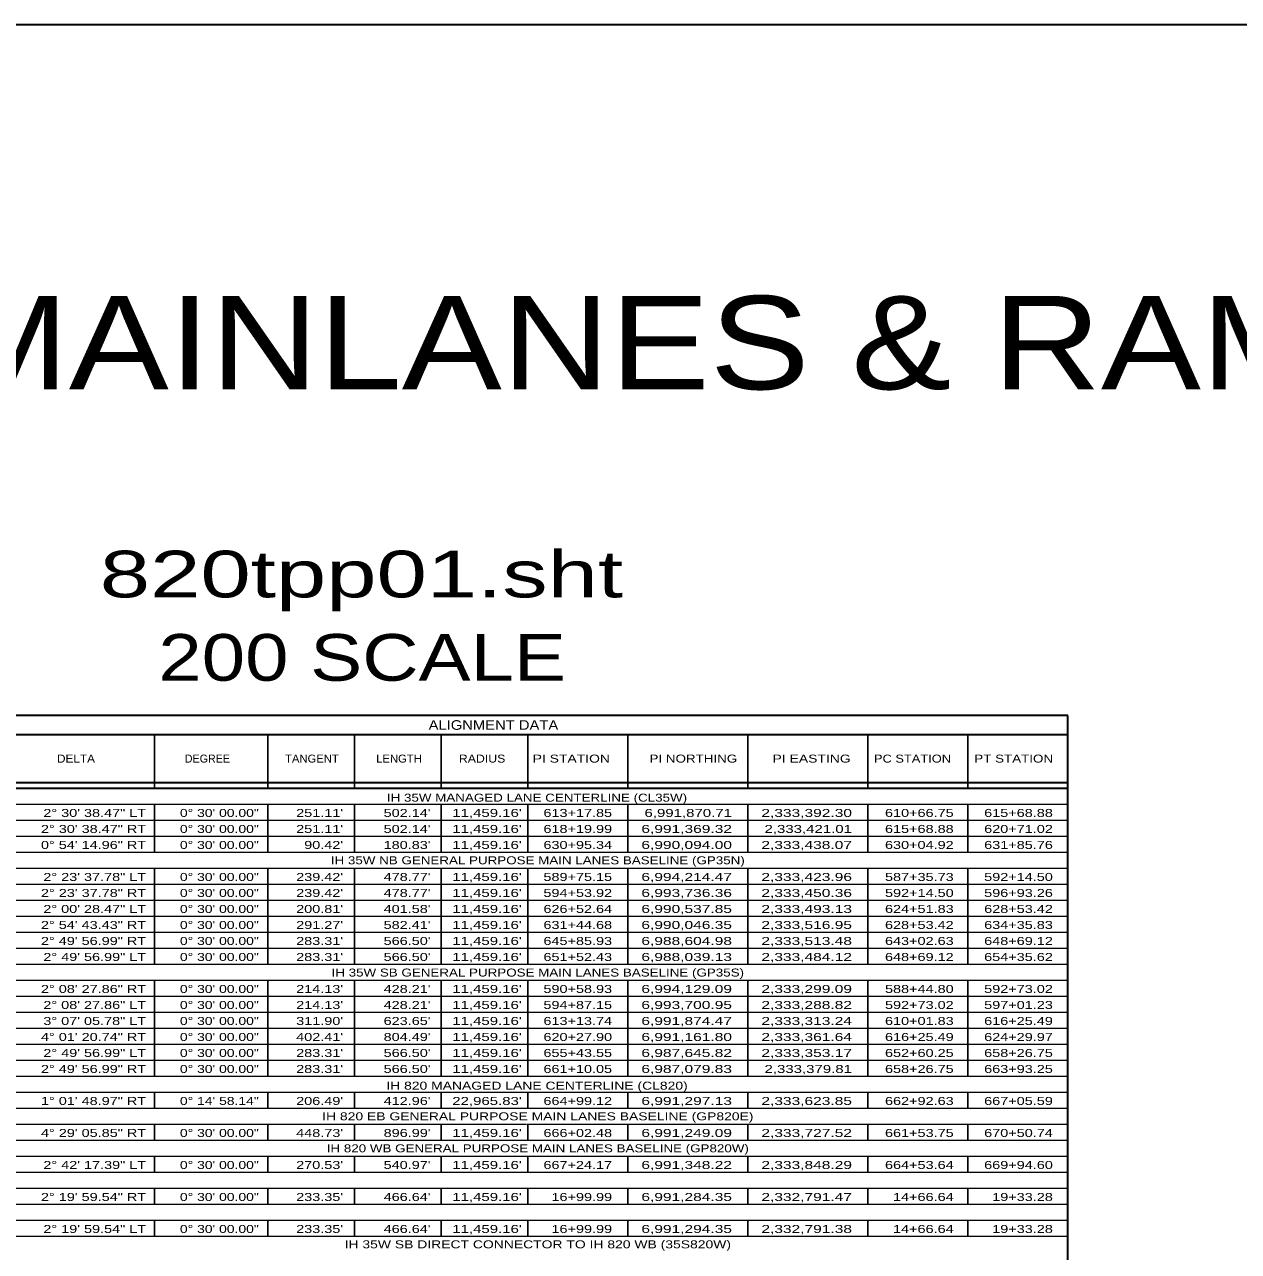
# Model space of a CAD drawing. Extents: x 1953053 to 1967065, y 7363860 to 7371201.
# Drawn here: x 1954045 to 1955866, y 7369361 to 7371201 of the extents above; entities that cross this region are included whole.
import ezdxf
from ezdxf.enums import TextEntityAlignment as Align

# ---------------------------------------------------------------- set-up
doc = ezdxf.new("R2010")
doc.units = 0
doc.header["$LTSCALE"] = 4.8
doc.layers.add('10', color=7, linetype='Continuous')
doc.layers.add('12', color=7, linetype='Continuous', lineweight=25)
doc.layers.add('62', color=7, linetype='Continuous', lineweight=35)

msp = doc.modelspace()

# ---------------------------------------------------------------- linework, layer by layer
at = {"layer": '12', "lineweight": 35}
for p, q in [((1955609.815, 7370164.879), (1953886.483, 7370164.879)), ((1955609.815, 7370055.746), (1955609.815, 7370164.879)), ((1953886.483, 7370136.079), (1955609.815, 7370136.079)), ((1953886.483, 7370064.079), (1955609.815, 7370064.079)), ((1953886.483, 7370055.746), (1955609.815, 7370055.746)), ((1955609.815, 7367775.748), (1955609.815, 7370055.746))]:
    msp.add_line(p, q, dxfattribs=at)
at = {"layer": '12'}
for p, q in [((1954239.815, 7370136.079), (1954239.815, 7370055.746)), ((1954409.815, 7370136.079), (1954409.815, 7370055.746)), ((1954539.815, 7370136.079), (1954539.815, 7370055.746)), ((1954669.815, 7370136.079), (1954669.815, 7370055.746)), ((1954799.815, 7370136.079), (1954799.815, 7370055.746)), ((1954949.815, 7370136.079), (1954949.815, 7370055.746)), ((1955129.815, 7370136.079), (1955129.815, 7370055.746)), ((1955309.815, 7370136.079), (1955309.815, 7370055.746)), ((1955459.815, 7370136.079), (1955459.815, 7370055.746)), ((1954239.815, 7370031.746), (1954239.815, 7369959.746)), ((1954409.815, 7370031.746), (1954409.815, 7369959.746)), ((1954539.815, 7370031.746), (1954539.815, 7369959.746)), ((1954669.815, 7370031.746), (1954669.815, 7369959.746)), ((1954799.815, 7370031.746), (1954799.815, 7369959.746)), ((1954949.815, 7370031.746), (1954949.815, 7369959.746)), ((1955129.815, 7370031.746), (1955129.815, 7369959.746)), ((1955309.815, 7370031.746), (1955309.815, 7369959.746)), ((1955459.815, 7370031.746), (1955459.815, 7369959.746)), ((1954239.815, 7369935.746), (1954239.815, 7369791.746)), ((1954409.815, 7369935.746), (1954409.815, 7369791.746)), ((1954539.815, 7369935.746), (1954539.815, 7369791.746)), ((1954669.815, 7369935.746), (1954669.815, 7369791.746)), ((1954799.815, 7369935.746), (1954799.815, 7369791.746)), ((1954949.815, 7369935.746), (1954949.815, 7369791.746)), ((1955129.815, 7369935.746), (1955129.815, 7369791.746)), ((1955309.815, 7369935.746), (1955309.815, 7369791.746)), ((1955459.815, 7369935.746), (1955459.815, 7369791.746)), ((1954239.815, 7369767.746), (1954239.815, 7369623.746)), ((1954409.815, 7369767.746), (1954409.815, 7369623.746)), ((1954539.815, 7369767.746), (1954539.815, 7369623.746)), ((1954669.815, 7369767.746), (1954669.815, 7369623.746)), ((1954799.815, 7369767.746), (1954799.815, 7369623.746)), ((1954949.815, 7369767.746), (1954949.815, 7369623.746)), ((1955129.815, 7369767.746), (1955129.815, 7369623.746)), ((1955309.815, 7369767.746), (1955309.815, 7369623.746)), ((1955459.815, 7369767.746), (1955459.815, 7369623.746)), ((1954239.815, 7369599.746), (1954239.815, 7369575.746)), ((1954409.815, 7369599.746), (1954409.815, 7369575.746)), ((1954539.815, 7369599.746), (1954539.815, 7369575.746)), ((1954669.815, 7369599.746), (1954669.815, 7369575.746)), ((1954799.815, 7369599.746), (1954799.815, 7369575.746)), ((1954949.815, 7369599.746), (1954949.815, 7369575.746)), ((1955129.815, 7369599.746), (1955129.815, 7369575.746)), ((1955309.815, 7369599.746), (1955309.815, 7369575.746)), ((1955459.815, 7369599.746), (1955459.815, 7369575.746)), ((1954239.815, 7369551.746), (1954239.815, 7369527.748)), ((1954409.815, 7369551.746), (1954409.815, 7369527.748)), ((1954539.815, 7369551.746), (1954539.815, 7369527.748)), ((1954669.815, 7369551.746), (1954669.815, 7369527.748)), ((1954799.815, 7369551.746), (1954799.815, 7369527.748)), ((1954949.815, 7369551.746), (1954949.815, 7369527.748)), ((1955129.815, 7369551.746), (1955129.815, 7369527.748)), ((1955309.815, 7369551.746), (1955309.815, 7369527.748)), ((1955459.815, 7369551.746), (1955459.815, 7369527.748)), ((1954239.815, 7369503.748), (1954239.815, 7369479.748)), ((1954409.815, 7369503.748), (1954409.815, 7369479.748)), ((1954539.815, 7369503.748), (1954539.815, 7369479.748)), ((1954669.815, 7369503.748), (1954669.815, 7369479.748)), ((1954799.815, 7369503.748), (1954799.815, 7369479.748)), ((1954949.815, 7369503.748), (1954949.815, 7369479.748)), ((1955129.815, 7369503.748), (1955129.815, 7369479.748)), ((1955309.815, 7369503.748), (1955309.815, 7369479.748)), ((1955459.815, 7369503.748), (1955459.815, 7369479.748)), ((1954239.815, 7369455.748), (1954239.815, 7369431.748)), ((1954409.815, 7369455.748), (1954409.815, 7369431.748)), ((1954539.815, 7369455.748), (1954539.815, 7369431.748)), ((1954669.815, 7369455.748), (1954669.815, 7369431.748)), ((1954799.815, 7369455.748), (1954799.815, 7369431.748)), ((1954949.815, 7369455.748), (1954949.815, 7369431.748)), ((1955129.815, 7369455.748), (1955129.815, 7369431.748)), ((1955309.815, 7369455.748), (1955309.815, 7369431.748)), ((1955459.815, 7369455.748), (1955459.815, 7369431.748)), ((1954239.815, 7369407.748), (1954239.815, 7369383.748)), ((1954409.815, 7369407.748), (1954409.815, 7369383.748)), ((1954539.815, 7369407.748), (1954539.815, 7369383.748)), ((1954669.815, 7369407.748), (1954669.815, 7369383.748)), ((1954799.815, 7369407.748), (1954799.815, 7369383.748)), ((1954949.815, 7369407.748), (1954949.815, 7369383.748)), ((1955129.815, 7369407.748), (1955129.815, 7369383.748)), ((1955309.815, 7369407.748), (1955309.815, 7369383.748)), ((1955459.815, 7369407.748), (1955459.815, 7369383.748))]:
    msp.add_line(p, q, dxfattribs=at)
at = {"layer": '12', "lineweight": 13}
for p, q in [((1953886.483, 7370031.746), (1955609.815, 7370031.746)), ((1953886.483, 7370007.746), (1955609.815, 7370007.746)), ((1953886.483, 7369983.746), (1955609.815, 7369983.746)), ((1953886.483, 7369959.746), (1955609.815, 7369959.746)), ((1953886.483, 7369935.746), (1955609.815, 7369935.746)), ((1953886.483, 7369911.746), (1955609.815, 7369911.746)), ((1953886.483, 7369887.746), (1955609.815, 7369887.746)), ((1953886.483, 7369887.746), (1955609.815, 7369887.746)), ((1953886.483, 7369863.746), (1955609.815, 7369863.746)), ((1953886.483, 7369839.746), (1955609.815, 7369839.746)), ((1953886.483, 7369815.746), (1955609.815, 7369815.746)), ((1953886.483, 7369791.746), (1955609.815, 7369791.746)), ((1953886.483, 7369767.746), (1955609.815, 7369767.746)), ((1953886.483, 7369743.746), (1955609.815, 7369743.746)), ((1953886.483, 7369719.746), (1955609.815, 7369719.746)), ((1953886.483, 7369695.746), (1955609.815, 7369695.746)), ((1953886.483, 7369671.746), (1955609.815, 7369671.746)), ((1953886.483, 7369647.746), (1955609.815, 7369647.746)), ((1953886.483, 7369623.746), (1955609.815, 7369623.746)), ((1953886.483, 7369599.746), (1955609.815, 7369599.746)), ((1953886.483, 7369575.746), (1955609.815, 7369575.746)), ((1953886.483, 7369551.746), (1954797.799, 7369551.746)), ((1954798.805, 7369551.746), (1955609.815, 7369551.746)), ((1953886.483, 7369527.748), (1955609.815, 7369527.748)), ((1953886.483, 7369503.748), (1955609.815, 7369503.748)), ((1953886.483, 7369479.748), (1955609.815, 7369479.748)), ((1953886.483, 7369455.748), (1955609.815, 7369455.748)), ((1953886.483, 7369431.748), (1955609.815, 7369431.748)), ((1953886.483, 7369407.748), (1955609.815, 7369407.748)), ((1953886.483, 7369383.748), (1955609.815, 7369383.748))]:
    msp.add_line(p, q, dxfattribs=at)
at = {"layer": '62'}
msp.add_lwpolyline([(1953052.784, 7371201.108), (1967065.314, 7371201.108), (1967065.314, 7363859.877), (1953052.784, 7363859.877)], close=True, dxfattribs=at)

# ---------------------------------------------------------------- texts
at = {"layer": '10'}
for s, width, p in [('IH 35W MANAGED LANE CENTERLINE (CL35W)', 1.25, (1954813.606, 7370035.509)), ('IH 35W NB GENERAL PURPOSE MAIN LANES BASELINE (GP35N)', 1.25, (1954814.815, 7369941.54)), ('IH 35W SB GENERAL PURPOSE MAIN LANES BASELINE (GP35S)', 1.25, (1954814.815, 7369773.158)), ('IH 820 MANAGED LANE CENTERLINE (CL820)', 1.3, (1954813.606, 7369603.509)), ('IH 820 EB GENERAL PURPOSE MAIN LANES BASELINE (GP820E)', 1.3, (1954814.816, 7369557.54)), ('IH 820 WB GENERAL PURPOSE MAIN LANES BASELINE (GP820W)', 1.25, (1954814.816, 7369509.542)), ('IH 35W SB DIRECT CONNECTOR TO IH 820 WB (35S820W)', 1.3, (1954814.815, 7369365.542))]:
    msp.add_text(s, height=12, dxfattribs=dict(at, width=width)).set_placement(p, align=Align.CENTER)
for s, width, p in [('2° 30\' 38.47" LT', 1.35, (1954227.337, 7370012.573)), ('0° 30\' 00.00"', 1.3, (1954396.332, 7370012.573)), ("251.11'", 1.35, (1954522.742, 7370012.573)), ("502.14'", 1.35, (1954653.939, 7370012.573)), ("11,459.16'", 1.4, (1954790.708, 7370012.573)), ('613+17.85', 1.35, (1954926.252, 7370012.573)), ('6,991,870.71', 1.4, (1955106.017, 7370012.573)), ('2,333,392.30', 1.45, (1955286.017, 7370012.573)), ('610+66.75', 1.35, (1955438.595, 7370012.573)), ('615+68.88', 1.35, (1955587.327, 7370012.573)), ('2° 30\' 38.47" RT', 1.35, (1954227.337, 7369988.573)), ('0° 30\' 00.00"', 1.3, (1954396.332, 7369988.573)), ("251.11'", 1.35, (1954522.742, 7369988.573)), ("502.14'", 1.35, (1954653.939, 7369988.573)), ("11,459.16'", 1.4, (1954790.708, 7369988.573)), ('618+19.99', 1.35, (1954926.252, 7369988.573)), ('6,991,369.32', 1.45, (1955106.017, 7369988.573)), ('2,333,421.01', 1.4, (1955286.017, 7369988.573)), ('615+68.88', 1.35, (1955438.595, 7369988.573)), ('620+71.02', 1.35, (1955587.327, 7369988.573)), ('0° 54\' 14.96" RT', 1.35, (1954227.337, 7369964.573)), ('0° 30\' 00.00"', 1.3, (1954396.332, 7369964.573)), ("90.42'", 1.35, (1954522.742, 7369964.573)), ("180.83'", 1.35, (1954653.939, 7369964.573)), ("11,459.16'", 1.4, (1954790.708, 7369964.573)), ('630+95.34', 1.35, (1954926.252, 7369964.573)), ('6,990,094.00', 1.45, (1955106.017, 7369964.573)), ('2,333,438.07', 1.45, (1955286.017, 7369964.573)), ('630+04.92', 1.35, (1955438.595, 7369964.573)), ('631+85.76', 1.35, (1955587.327, 7369964.573)), ('2° 23\' 37.78" LT', 1.35, (1954227.337, 7369916.573)), ('0° 30\' 00.00"', 1.3, (1954396.332, 7369916.573)), ("239.42'", 1.35, (1954522.742, 7369916.573)), ("478.77'", 1.35, (1954653.939, 7369916.573)), ("11,459.16'", 1.4, (1954790.708, 7369916.573)), ('589+75.15', 1.35, (1954926.252, 7369916.573)), ('6,994,214.47', 1.45, (1955106.017, 7369916.573)), ('2,333,423.96', 1.45, (1955286.017, 7369916.573)), ('587+35.73', 1.35, (1955438.595, 7369916.573)), ('592+14.50', 1.35, (1955587.327, 7369916.573)), ('2° 23\' 37.78" RT', 1.35, (1954227.337, 7369892.573)), ('0° 30\' 00.00"', 1.3, (1954396.332, 7369892.573)), ("239.42'", 1.35, (1954522.742, 7369892.573)), ("478.77'", 1.35, (1954653.939, 7369892.573)), ("11,459.16'", 1.4, (1954790.708, 7369892.573)), ('594+53.92', 1.35, (1954926.252, 7369892.573)), ('6,993,736.36', 1.45, (1955106.017, 7369892.573)), ('2,333,450.36', 1.45, (1955286.017, 7369892.573)), ('592+14.50', 1.35, (1955438.595, 7369892.573)), ('596+93.26', 1.35, (1955587.327, 7369892.573)), ('2° 00\' 28.47" LT', 1.35, (1954227.337, 7369868.573)), ('0° 30\' 00.00"', 1.3, (1954396.332, 7369868.573)), ("200.81'", 1.35, (1954522.742, 7369868.573)), ("401.58'", 1.35, (1954653.939, 7369868.573)), ("11,459.16'", 1.4, (1954790.708, 7369868.573)), ('626+52.64', 1.35, (1954926.252, 7369868.573)), ('6,990,537.85', 1.45, (1955106.017, 7369868.573)), ('2,333,493.13', 1.45, (1955286.017, 7369868.573)), ('624+51.83', 1.35, (1955438.595, 7369868.573)), ('628+53.42', 1.35, (1955587.327, 7369868.573)), ('2° 54\' 43.43" RT', 1.35, (1954227.337, 7369844.573)), ('0° 30\' 00.00"', 1.3, (1954396.332, 7369844.573)), ("291.27'", 1.35, (1954522.742, 7369844.573)), ("582.41'", 1.35, (1954653.939, 7369844.573)), ("11,459.16'", 1.4, (1954790.708, 7369844.573)), ('631+44.68', 1.35, (1954926.252, 7369844.573)), ('6,990,046.35', 1.45, (1955106.017, 7369844.573)), ('2,333,516.95', 1.45, (1955286.017, 7369844.573)), ('628+53.42', 1.35, (1955438.595, 7369844.573)), ('634+35.83', 1.35, (1955587.327, 7369844.573)), ('2° 49\' 56.99" RT', 1.35, (1954227.337, 7369820.573)), ('0° 30\' 00.00"', 1.3, (1954396.332, 7369820.573)), ("283.31'", 1.35, (1954522.742, 7369820.573)), ("566.50'", 1.35, (1954653.939, 7369820.573)), ("11,459.16'", 1.4, (1954790.708, 7369820.573)), ('645+85.93', 1.35, (1954926.252, 7369820.573)), ('6,988,604.98', 1.45, (1955106.017, 7369820.573)), ('2,333,513.48', 1.45, (1955286.017, 7369820.573)), ('643+02.63', 1.35, (1955438.595, 7369820.573)), ('648+69.12', 1.35, (1955587.327, 7369820.573)), ('2° 49\' 56.99" LT', 1.35, (1954227.337, 7369796.573)), ('0° 30\' 00.00"', 1.3, (1954396.332, 7369796.573)), ("283.31'", 1.35, (1954522.742, 7369796.573)), ("566.50'", 1.35, (1954653.939, 7369796.573)), ("11,459.16'", 1.4, (1954790.708, 7369796.573)), ('651+52.43', 1.35, (1954926.252, 7369796.573)), ('6,988,039.13', 1.45, (1955106.017, 7369796.573)), ('2,333,484.12', 1.45, (1955286.017, 7369796.573)), ('648+69.12', 1.35, (1955438.595, 7369796.573)), ('654+35.62', 1.35, (1955587.327, 7369796.573)), ('2° 08\' 27.86" RT', 1.35, (1954227.337, 7369748.573)), ('0° 30\' 00.00"', 1.3, (1954396.332, 7369748.573)), ("214.13'", 1.35, (1954522.742, 7369748.573)), ("428.21'", 1.35, (1954653.939, 7369748.573)), ("11,459.16'", 1.4, (1954790.708, 7369748.573)), ('590+58.93', 1.35, (1954926.252, 7369748.573)), ('6,994,129.09', 1.45, (1955106.017, 7369748.573)), ('2,333,299.09', 1.45, (1955286.017, 7369748.573)), ('588+44.80', 1.35, (1955438.595, 7369748.573)), ('592+73.02', 1.35, (1955587.327, 7369748.573)), ('2° 08\' 27.86" LT', 1.35, (1954227.337, 7369724.573)), ('0° 30\' 00.00"', 1.3, (1954396.332, 7369724.573)), ("214.13'", 1.35, (1954522.742, 7369724.573)), ("428.21'", 1.35, (1954653.939, 7369724.573)), ("11,459.16'", 1.4, (1954790.708, 7369724.573)), ('594+87.15', 1.35, (1954926.252, 7369724.573)), ('6,993,700.95', 1.45, (1955106.017, 7369724.573)), ('2,333,288.82', 1.45, (1955286.017, 7369724.573)), ('592+73.02', 1.35, (1955438.595, 7369724.573)), ('597+01.23', 1.35, (1955587.327, 7369724.573)), ('3° 07\' 05.78" LT', 1.35, (1954227.337, 7369700.573)), ('0° 30\' 00.00"', 1.3, (1954396.332, 7369700.573)), ("311.90'", 1.35, (1954522.742, 7369700.573)), ("623.65'", 1.35, (1954653.939, 7369700.573)), ("11,459.16'", 1.4, (1954790.708, 7369700.573)), ('613+13.74', 1.35, (1954926.252, 7369700.573)), ('6,991,874.47', 1.45, (1955106.017, 7369700.573)), ('2,333,313.24', 1.45, (1955286.017, 7369700.573)), ('610+01.83', 1.35, (1955438.595, 7369700.573)), ('616+25.49', 1.35, (1955587.327, 7369700.573)), ('4° 01\' 20.74" RT', 1.35, (1954227.337, 7369676.573)), ('0° 30\' 00.00"', 1.3, (1954396.332, 7369676.573)), ("402.41'", 1.35, (1954522.742, 7369676.573)), ("804.49'", 1.35, (1954653.939, 7369676.573)), ("11,459.16'", 1.4, (1954790.708, 7369676.573)), ('620+27.90', 1.35, (1954926.252, 7369676.573)), ('6,991,161.80', 1.45, (1955106.017, 7369676.573)), ('2,333,361.64', 1.45, (1955286.017, 7369676.573)), ('616+25.49', 1.35, (1955438.595, 7369676.573)), ('624+29.97', 1.35, (1955587.327, 7369676.573)), ('2° 49\' 56.99" LT', 1.35, (1954227.337, 7369652.573)), ('0° 30\' 00.00"', 1.3, (1954396.332, 7369652.573)), ("283.31'", 1.35, (1954522.742, 7369652.573)), ("566.50'", 1.35, (1954653.939, 7369652.573)), ("11,459.16'", 1.4, (1954790.708, 7369652.573)), ('655+43.55', 1.35, (1954926.252, 7369652.573)), ('6,987,645.82', 1.45, (1955106.017, 7369652.573)), ('2,333,353.17', 1.45, (1955286.017, 7369652.573)), ('652+60.25', 1.35, (1955438.595, 7369652.573)), ('658+26.75', 1.35, (1955587.327, 7369652.573)), ('2° 49\' 56.99" RT', 1.35, (1954227.337, 7369628.573)), ('0° 30\' 00.00"', 1.3, (1954396.332, 7369628.573)), ("283.31'", 1.35, (1954522.742, 7369628.573)), ("566.50'", 1.35, (1954653.939, 7369628.573)), ("11,459.16'", 1.4, (1954790.708, 7369628.573)), ('661+10.05', 1.35, (1954926.252, 7369628.573)), ('6,987,079.83', 1.45, (1955106.017, 7369628.573)), ('2,333,379.81', 1.4, (1955286.017, 7369628.573)), ('658+26.75', 1.35, (1955438.595, 7369628.573)), ('663+93.25', 1.35, (1955587.327, 7369628.573)), ('1° 01\' 48.97" RT', 1.35, (1954227.337, 7369580.573)), ('0° 14\' 58.14"', 1.3, (1954396.332, 7369580.573)), ("206.49'", 1.35, (1954522.742, 7369580.573)), ("412.96'", 1.35, (1954653.939, 7369580.573)), ("22,965.83'", 1.4, (1954790.708, 7369580.573)), ('664+99.12', 1.35, (1954926.252, 7369580.573)), ('6,991,297.13', 1.45, (1955106.017, 7369580.573)), ('2,333,623.85', 1.45, (1955286.017, 7369580.573)), ('662+92.63', 1.35, (1955438.595, 7369580.573)), ('667+05.59', 1.35, (1955587.327, 7369580.573)), ('4° 29\' 05.85" RT', 1.35, (1954227.337, 7369532.575)), ('0° 30\' 00.00"', 1.3, (1954396.332, 7369532.575)), ("448.73'", 1.35, (1954522.742, 7369532.575)), ("896.99'", 1.35, (1954653.939, 7369532.575)), ("11,459.16'", 1.4, (1954790.708, 7369532.575)), ('666+02.48', 1.35, (1954926.252, 7369532.575)), ('6,991,249.09', 1.45, (1955106.017, 7369532.575)), ('2,333,727.52', 1.45, (1955286.017, 7369532.575)), ('661+53.75', 1.35, (1955438.595, 7369532.575)), ('670+50.74', 1.35, (1955587.327, 7369532.575)), ('2° 42\' 17.39" LT', 1.35, (1954227.337, 7369484.575)), ('0° 30\' 00.00"', 1.3, (1954396.332, 7369484.575)), ("270.53'", 1.35, (1954522.742, 7369484.575)), ("540.97'", 1.35, (1954653.939, 7369484.575)), ("11,459.16'", 1.4, (1954790.708, 7369484.575)), ('667+24.17', 1.35, (1954926.252, 7369484.575)), ('6,991,348.22', 1.45, (1955106.017, 7369484.575)), ('2,333,848.29', 1.45, (1955286.017, 7369484.575)), ('664+53.64', 1.35, (1955438.595, 7369484.575)), ('669+94.60', 1.35, (1955587.327, 7369484.575)), ('2° 19\' 59.54" RT', 1.35, (1954227.337, 7369436.575)), ('0° 30\' 00.00"', 1.3, (1954396.332, 7369436.575)), ("233.35'", 1.35, (1954522.742, 7369436.575)), ("466.64'", 1.35, (1954653.939, 7369436.575)), ("11,459.16'", 1.4, (1954790.708, 7369436.575)), ('16+99.99', 1.35, (1954926.252, 7369436.575)), ('6,991,284.35', 1.45, (1955106.017, 7369436.575)), ('2,332,791.47', 1.45, (1955286.017, 7369436.575)), ('14+66.64', 1.35, (1955438.595, 7369436.575)), ('19+33.28', 1.35, (1955587.327, 7369436.575)), ('2° 19\' 59.54" LT', 1.35, (1954227.337, 7369388.575)), ('0° 30\' 00.00"', 1.3, (1954396.332, 7369388.575)), ("233.35'", 1.35, (1954522.742, 7369388.575)), ("466.64'", 1.35, (1954653.939, 7369388.575)), ("11,459.16'", 1.4, (1954790.708, 7369388.575)), ('16+99.99', 1.35, (1954926.252, 7369388.575)), ('6,991,294.35', 1.45, (1955106.017, 7369388.575)), ('2,332,791.38', 1.45, (1955286.017, 7369388.575)), ('14+66.64', 1.35, (1955438.595, 7369388.575)), ('19+33.28', 1.35, (1955587.327, 7369388.575))]:
    msp.add_text(s, height=12, dxfattribs=dict(at, width=width)).set_placement(p, align=Align.RIGHT)
at = {"layer": '12'}
for s, height, width, p in [('ALIGNMENT DATA', 14.4, 1.15, (1954748.256, 7370143.278)), ('DELTA', 12, 1.1, (1954122.106, 7370094.078)), ('TANGENT', 12, 1.05, (1954476.003, 7370094.078)), ('LENGTH', 12, 1.05, (1954606.638, 7370094.078)), ('RADIUS', 12, 1.15, (1954731.248, 7370094.078)), ('PI STATION', 12, 1.3, (1954865.052, 7370094.078)), ('PI NORTHING', 12, 1.25, (1955048.127, 7370094.078)), ('PI EASTING', 12, 1.3, (1955225.519, 7370094.078)), ('PC STATION', 12, 1.2, (1955376.824, 7370094.078)), ('PT STATION', 12, 1.25, (1955528.595, 7370094.078))]:
    msp.add_text(s, height=height, dxfattribs=dict(at, width=width)).set_placement(p, align=Align.CENTER)
msp.add_text('DEGREE', height=12, dxfattribs=at).set_placement((1954319.192, 7370094.078), align=Align.CENTER)
at = {"layer": '62'}
for s, height, width, p in [('MAINLANES & RAMPS', 140, 1.2, (1955110.243, 7370654.085)), ('820tpp01.sht', 70, 1.45, (1954550.239, 7370341.878)), ('200 SCALE', 70, 1.25, (1954551.348, 7370216.878))]:
    msp.add_text(s, height=height, dxfattribs=dict(at, width=width)).set_placement(p, align=Align.CENTER)

doc.saveas('drawing.dxf')
